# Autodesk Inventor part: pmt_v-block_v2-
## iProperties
Shininess: 64.0
Length Units: 11269
Angle Units: 11279
Time Units: 11290
Mass Units: 11283
Length Display Precision: 3
Angle Display Precision: 2
Compacted: True
Part Number: pmt_v-block_v2-
Document SubType Name: Modeling
Created: 2004-08
Designer: John Blackburn
Manufacturer: Standard
Standards Organization: Custom
Material: Aluminum-6061
Density: 0.0
Volumn: 0.0
Area: 0.0
PropertySet Name: Model Information
Control State: 0
Master: False
Checked Out: False
Author: John Blackburn
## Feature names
1. Extrusion1
2. Hole1
3. Hole4
4. Hole5
5. Hole6
